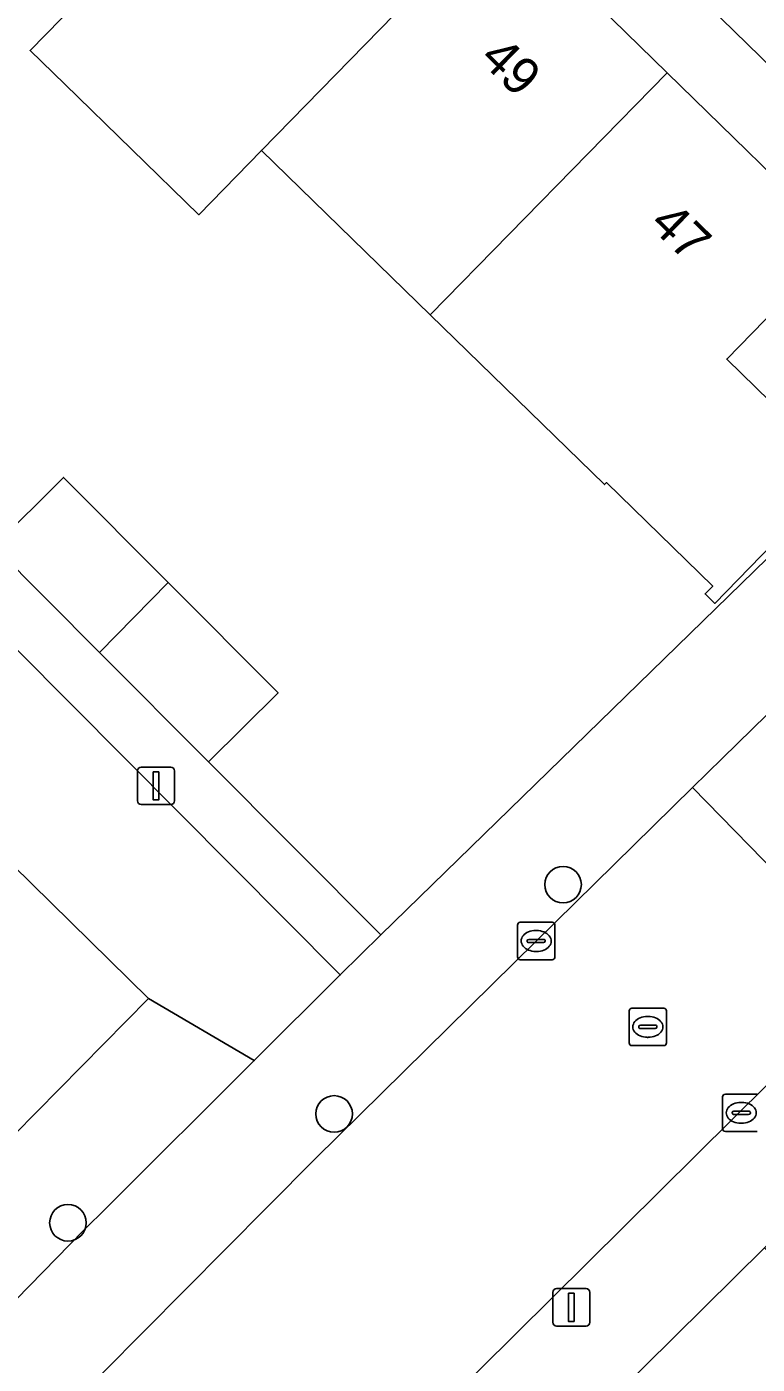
# Model space of a CAD drawing. Extents: x 159217 to 160349, y 381246 to 382172.
# Drawn here: x 159959.7 to 159979.23, y 381745.8 to 381781.59 of the extents above; entities that cross this region are included whole.
import ezdxf

# ---------------------------------------------------------------- set-up
doc = ezdxf.new("R2010")
doc.units = 0
for name, color, linetype in [('IMGEO_Boom', 7, 'Continuous'), ('IMGEO_Erf', 7, 'Continuous'), ('IMGEO_Groenvoorziening', 7, 'Continuous'), ('IMGEO_Kolk', 7, 'Continuous'), ('IMGEO_Lichtmast', 7, 'Continuous'), ('IMGEO_Pand', 7, 'Continuous'), ('IMGEO_Pand_nummerreeks', 7, 'Continuous'), ('IMGEO_Rijbaan_lokaal_open', 7, 'Continuous'), ('IMGEO_Rioolput', 7, 'Continuous'), ('IMGEO_Terreindeel_zand', 7, 'Continuous'), ('IMGEO_Voetpad_open', 7, 'Continuous')]:
    doc.layers.add(name, color=color, linetype=linetype)

msp = doc.modelspace()

# ---------------------------------------------------------------- linework, layer by layer
at = {"layer": 'IMGEO_Boom'}
for centre in [(159974.041, 381758.632), (159967.918, 381752.497), (159960.799, 381749.583)]:
    msp.add_circle(centre, 0.489, dxfattribs=at)
at = {"layer": 'IMGEO_Erf'}
for points in [[(159983.879, 381776.342), (159944.981, 381814.27)], [(159974.984, 381782.15), (159976.824, 381780.357), (159981.472, 381775.827), (159978.42, 381772.695), (159981.516, 381769.668), (159978.097, 381766.158), (159977.839, 381766.41), (159978.042, 381766.618), (159975.203, 381769.393), (159975.149, 381769.338), (159970.487, 381773.881), (159965.975, 381778.278), (159964.301, 381776.56), (159960.72, 381780.049), (159959.789, 381780.957), (159961.457, 381782.669)], [(159948.65, 381781.627), (159946.792, 381779.78), (159948.356, 381778.17), (159951.879, 381781.709), (159953.722, 381779.875), (159952.027, 381778.173), (159954.583, 381775.629), (159957.521, 381772.706), (159955.673, 381770.849), (159958.821, 381767.68), (159960.678, 381769.528), (159963.477, 381766.717), (159966.418, 381763.763), (159964.562, 381761.914), (159969.165, 381757.287), (159981.918, 381769.715), (159984.182, 381771.978)], [(159997.321, 381729.885), (159995.883, 381728.418), (159993.394, 381730.857), (159990.86, 381733.341), (159992.628, 381735.145), (159989.575, 381738.368), (159987.673, 381736.588), (159985.051, 381739.39), (159982.746, 381741.853), (159984.649, 381743.633), (159979.428, 381748.909), (159965.791, 381735.415)]]:
    msp.add_lwpolyline(points, dxfattribs=at)
at = {"layer": 'IMGEO_Groenvoorziening'}
for points in [[(159958.779, 381759.677), (159962.956, 381755.584), (159965.783, 381753.926), (159968.081, 381756.217), (159943.572, 381780.882)], [(159951.102, 381739.016), (159961.219, 381749.376), (159961.845, 381750), (159965.783, 381753.926), (159962.956, 381755.584), (159951.002, 381743.455)]]:
    msp.add_lwpolyline(points, dxfattribs=at)
at = {"layer": 'IMGEO_Kolk'}
for p, q in [((159972.821, 381756.698), (159972.821, 381757.55)), ((159972.896, 381757.624), (159973.748, 381757.624)), ((159973.822, 381757.55), (159973.822, 381756.698)), ((159973.309, 381757.404), (159973.334, 381757.404)), ((159973.08, 381757.118), (159973.08, 381757.13)), ((159973.518, 381757.081), (159973.12, 381757.081)), ((159973.123, 381757.167), (159973.521, 381757.167)), ((159973.332, 381756.844), (159973.307, 381756.844)), ((159973.564, 381757.13), (159973.564, 381757.118)), ((159973.748, 381756.624), (159972.896, 381756.624)), ((159978.306, 381752.099), (159978.306, 381752.951)), ((159978.381, 381753.025), (159979.233, 381753.025)), ((159978.608, 381752.568), (159979.006, 381752.568)), ((159978.794, 381752.805), (159978.819, 381752.805)), ((159978.565, 381752.519), (159978.565, 381752.531)), ((159979.003, 381752.482), (159978.605, 381752.482)), ((159978.817, 381752.245), (159978.792, 381752.245)), ((159979.049, 381752.531), (159979.049, 381752.519)), ((159979.233, 381752.025), (159978.381, 381752.025))]:
    msp.add_line(p, q, dxfattribs=at)
for points in [[(159972.821, 381756.698), (159972.821, 381757.55)], [(159972.896, 381757.624), (159973.748, 381757.624)], [(159973.822, 381757.55), (159973.822, 381756.698)], [(159973.748, 381756.624), (159972.896, 381756.624)], [(159978.306, 381752.099), (159978.306, 381752.951)], [(159978.381, 381753.025), (159979.233, 381753.025)], [(159979.233, 381752.025), (159978.381, 381752.025)]]:
    msp.add_lwpolyline(points, dxfattribs=at)
for centre, radius, start, end in [((159972.898, 381757.548), 0.0765, 91.552, 178.448), ((159972.898, 381757.548), 0.0765, 91.552, 178.448), ((159973.746, 381757.548), 0.0765, 1.552, 88.448), ((159973.746, 381757.548), 0.0765, 1.552, 88.448), ((159973.12, 381757.127), 0.0403, 85.8775, 175.7526), ((159973.117, 381757.117), 0.0366, 178.938, 274.7102), ((159973.521, 381757.124), 0.043, 264.8664, 352.4533), ((159973.525, 381757.129), 0.0386, 1.7309, 96.639), ((159972.898, 381756.7), 0.0765, 181.552, 268.448), ((159972.898, 381756.7), 0.0765, 181.552, 268.448), ((159973.746, 381756.7), 0.0765, 271.552, 358.448), ((159973.746, 381756.7), 0.0765, 271.552, 358.448), ((159978.383, 381752.949), 0.0765, 91.552, 178.448), ((159978.383, 381752.949), 0.0765, 91.552, 178.448), ((159978.605, 381752.528), 0.0403, 85.8775, 175.7526), ((159979.01, 381752.53), 0.0386, 1.7309, 96.639), ((159978.602, 381752.518), 0.0366, 178.938, 274.7102), ((159979.006, 381752.525), 0.043, 264.8664, 352.4533), ((159978.383, 381752.101), 0.0765, 181.552, 268.448), ((159978.383, 381752.101), 0.0765, 181.552, 268.448)]:
    msp.add_arc(centre, radius, start, end, dxfattribs=at)
for centre, major_axis, ratio, start_param, end_param in [((159973.308, 381757.124), (-0.387, 0.002), 0.722429, 4.712389, 7.853982), ((159973.333, 381757.124), (-0.39, 0.002), 0.717154, 1.570796, 4.712389), ((159978.793, 381752.525), (-0.387, 0.002), 0.722429, 4.712389, 7.853982), ((159978.818, 381752.525), (-0.39, 0.002), 0.717154, 1.570796, 4.712389)]:
    msp.add_ellipse(centre, major_axis=major_axis, ratio=ratio, start_param=start_param, end_param=end_param, dxfattribs=at)
at = {"layer": 'IMGEO_Lichtmast'}
for p, q in [((159962.659, 381760.874), (159962.659, 381761.674)), ((159962.659, 381761.674), (159962.659, 381760.874)), ((159962.759, 381761.774), (159963.549, 381761.774)), ((159963.549, 381761.774), (159962.759, 381761.774)), ((159963.649, 381761.674), (159963.649, 381760.874)), ((159963.649, 381760.874), (159963.649, 381761.674)), ((159963.549, 381760.774), (159962.759, 381760.774)), ((159962.759, 381760.774), (159963.549, 381760.774)), ((159973.765, 381746.921), (159973.765, 381747.721)), ((159973.765, 381747.721), (159973.765, 381746.921)), ((159973.865, 381747.821), (159974.655, 381747.821)), ((159974.655, 381747.821), (159973.865, 381747.821)), ((159974.755, 381747.721), (159974.755, 381746.921)), ((159974.755, 381746.921), (159974.755, 381747.721)), ((159974.655, 381746.821), (159973.865, 381746.821)), ((159973.865, 381746.821), (159974.655, 381746.821))]:
    msp.add_line(p, q, dxfattribs=at)
for points in [[(159963.079, 381761.649), (159963.229, 381761.649), (159963.229, 381760.899), (159963.079, 381760.899), (159963.079, 381761.649)], [(159974.185, 381747.696), (159974.335, 381747.696), (159974.335, 381746.946), (159974.185, 381746.946), (159974.185, 381747.696)]]:
    msp.add_lwpolyline(points, dxfattribs=at)
for centre, start, end in [((159962.759, 381761.674), 90, 180), ((159962.759, 381761.674), 90, 180), ((159963.549, 381761.674), 0, 90), ((159963.549, 381761.674), 360, 90), ((159962.759, 381760.874), 180, 270), ((159962.759, 381760.874), 180, 270), ((159963.549, 381760.874), 270, 0), ((159963.549, 381760.874), 270, 0), ((159973.865, 381747.721), 90, 180), ((159973.865, 381747.721), 90, 180), ((159974.655, 381747.721), 0, 90), ((159974.655, 381747.721), 360, 90), ((159973.865, 381746.921), 180, 270), ((159973.865, 381746.921), 180, 270), ((159974.655, 381746.921), 270, 0), ((159974.655, 381746.921), 270, 0)]:
    msp.add_arc(centre, 0.1, start, end, dxfattribs=at)
at = {"layer": 'IMGEO_Pand'}
for points in [[(159972.303, 381784.76), (159967.79, 381789.155), (159961.457, 381782.669), (159959.789, 381780.957), (159960.72, 381780.049), (159964.301, 381776.56), (159965.975, 381778.278)], [(159970.487, 381773.881), (159976.824, 381780.357), (159974.984, 381782.15), (159972.303, 381784.76), (159965.975, 381778.278)], [(159970.487, 381773.881), (159975.149, 381769.338), (159975.203, 381769.393), (159978.042, 381766.618), (159977.839, 381766.41), (159978.097, 381766.158), (159981.516, 381769.668), (159978.42, 381772.695), (159981.472, 381775.827), (159976.824, 381780.357)], [(159961.644, 381764.844), (159963.477, 381766.717), (159960.678, 381769.528), (159958.821, 381767.68)], [(159961.644, 381764.844), (159964.562, 381761.914), (159966.418, 381763.763), (159963.477, 381766.717)]]:
    msp.add_lwpolyline(points, close=True, dxfattribs=at)
at = {"layer": 'IMGEO_Rijbaan_lokaal_open'}
msp.add_lwpolyline([(159980.881, 381764.533), (159980.287, 381763.953), (159978.303, 381762.016), (159977.503, 381761.23), (159982.428, 381756.18), (159983.195, 381756.957), (159985.168, 381758.885), (159985.791, 381759.5)], close=True, dxfattribs=at)
msp.add_lwpolyline([(159964.09, 381737.995), (159982.428, 381756.18), (159977.503, 381761.23), (159973.323, 381757.123), (159967.429, 381751.315), (159966.126, 381750), (159961.743, 381745.577), (159959.666, 381743.451), (159958.803, 381742.588), (159953.054, 381736.646), (159944.522, 381727.792), (159942.659, 381725.828), (159941.73, 381724.849), (159946.781, 381720.023), (159947.694, 381720.953), (159951.478, 381724.809), (159952.525, 381725.938), (159963.213, 381736.961)], dxfattribs=at)
at = {"layer": 'IMGEO_Rioolput'}
for p, q in [((159975.807, 381754.4), (159975.807, 381755.252)), ((159975.882, 381755.326), (159976.734, 381755.326)), ((159976.295, 381755.106), (159976.32, 381755.106)), ((159976.808, 381755.252), (159976.808, 381754.4)), ((159976.066, 381754.82), (159976.066, 381754.832)), ((159976.504, 381754.783), (159976.106, 381754.783)), ((159976.109, 381754.869), (159976.507, 381754.869)), ((159976.55, 381754.832), (159976.55, 381754.82)), ((159976.734, 381754.326), (159975.882, 381754.326)), ((159976.318, 381754.546), (159976.293, 381754.546))]:
    msp.add_line(p, q, dxfattribs=at)
for points in [[(159975.807, 381754.4), (159975.807, 381755.252)], [(159975.882, 381755.326), (159976.734, 381755.326)], [(159976.808, 381755.252), (159976.808, 381754.4)], [(159976.734, 381754.326), (159975.882, 381754.326)]]:
    msp.add_lwpolyline(points, dxfattribs=at)
for centre, radius, start, end in [((159975.884, 381755.25), 0.0765, 91.552, 178.448), ((159975.884, 381755.25), 0.0765, 91.552, 178.448), ((159976.732, 381755.25), 0.0765, 1.552, 88.448), ((159976.732, 381755.25), 0.0765, 1.552, 88.448), ((159976.106, 381754.829), 0.0403, 85.8775, 175.7526), ((159976.103, 381754.819), 0.0366, 178.938, 274.7102), ((159976.507, 381754.826), 0.043, 264.8664, 352.4533), ((159976.511, 381754.831), 0.0386, 1.7309, 96.639), ((159975.884, 381754.402), 0.0765, 181.552, 268.448), ((159975.884, 381754.402), 0.0765, 181.552, 268.448), ((159976.732, 381754.402), 0.0765, 271.552, 358.448), ((159976.732, 381754.402), 0.0765, 271.552, 358.448)]:
    msp.add_arc(centre, radius, start, end, dxfattribs=at)
for centre, major_axis, ratio, start_param, end_param in [((159976.294, 381754.826), (-0.387, 0.002), 0.722429, 4.712389, 7.853982), ((159976.319, 381754.826), (-0.39, 0.002), 0.717154, 1.570796, 4.712389)]:
    msp.add_ellipse(centre, major_axis=major_axis, ratio=ratio, start_param=start_param, end_param=end_param, dxfattribs=at)
at = {"layer": 'IMGEO_Terreindeel_zand'}
msp.add_lwpolyline([(159957.868, 381760.57), (159957.241, 381761.185), (159952.335, 381756.178), (159949.513, 381753.297), (159945.339, 381749.037), (159946.808, 381747.589), (159951.002, 381743.455), (159962.956, 381755.584), (159958.779, 381759.677)], close=True, dxfattribs=at)
at = {"layer": 'IMGEO_Voetpad_open'}
for points in [[(159944.981, 381814.27), (159983.879, 381776.342)], [(159984.182, 381771.978), (159981.918, 381769.715), (159969.165, 381757.287), (159968.081, 381756.217), (159965.783, 381753.926), (159961.845, 381750), (159961.219, 381749.376), (159951.102, 381739.016)], [(159961.743, 381745.577), (159966.126, 381750), (159967.429, 381751.315), (159973.323, 381757.123), (159977.503, 381761.23), (159978.303, 381762.016), (159980.287, 381763.953), (159980.881, 381764.533), (159983.039, 381766.619), (159987.385, 381770.773)], [(159993.044, 381766.543), (159992.268, 381765.818), (159990.289, 381763.908), (159986.691, 381760.388), (159985.791, 381759.5), (159985.168, 381758.885), (159983.195, 381756.957), (159982.428, 381756.18), (159964.09, 381737.995)], [(159962.426, 381732.044), (159965.791, 381735.415), (159979.428, 381748.909), (159980.53, 381750)]]:
    msp.add_lwpolyline(points, dxfattribs=at)
msp.add_lwpolyline([(159943.572, 381780.882), (159968.081, 381756.217), (159969.165, 381757.287), (159964.562, 381761.914), (159961.644, 381764.844), (159958.821, 381767.68), (159955.673, 381770.849), (159952.753, 381773.755), (159949.916, 381776.578), (159948.356, 381778.17), (159946.792, 381779.78), (159943.882, 381782.706), (159943.542, 381783.048), (159941.857, 381781.334), (159938.971, 381778.46), (159936.097, 381775.597), (159932.926, 381772.458), (159930.039, 381769.6), (159927.148, 381766.737), (159925.088, 381764.697), (159925.115, 381764.67), (159924.33, 381763.872), (159925.447, 381762.9)], close=True, dxfattribs=at)

# ---------------------------------------------------------------- texts
at = {"layer": 'IMGEO_Pand_nummerreeks'}
for s, p in [('49', (159971.77, 381780.696)), ('47', (159976.317, 381776.268))]:
    msp.add_text(s, height=1, rotation=315.7588, dxfattribs=at).set_placement(p)

doc.saveas('drawing.dxf')
